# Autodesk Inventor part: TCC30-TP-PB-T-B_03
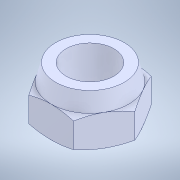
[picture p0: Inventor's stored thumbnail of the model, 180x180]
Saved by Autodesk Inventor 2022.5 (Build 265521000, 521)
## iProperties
Created: 2023-09
Part Number: TCC30-TP-PB-T-B_03
Material: 一般
Document SubType Name: Modeling
Designer: ImaoCorp
Density: 1 g/cm^3
Appearance: 既定
Author: ImaoCorp
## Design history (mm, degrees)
feature "TCC30-TP-PB-T-B_03"
node "ソリッド1"
